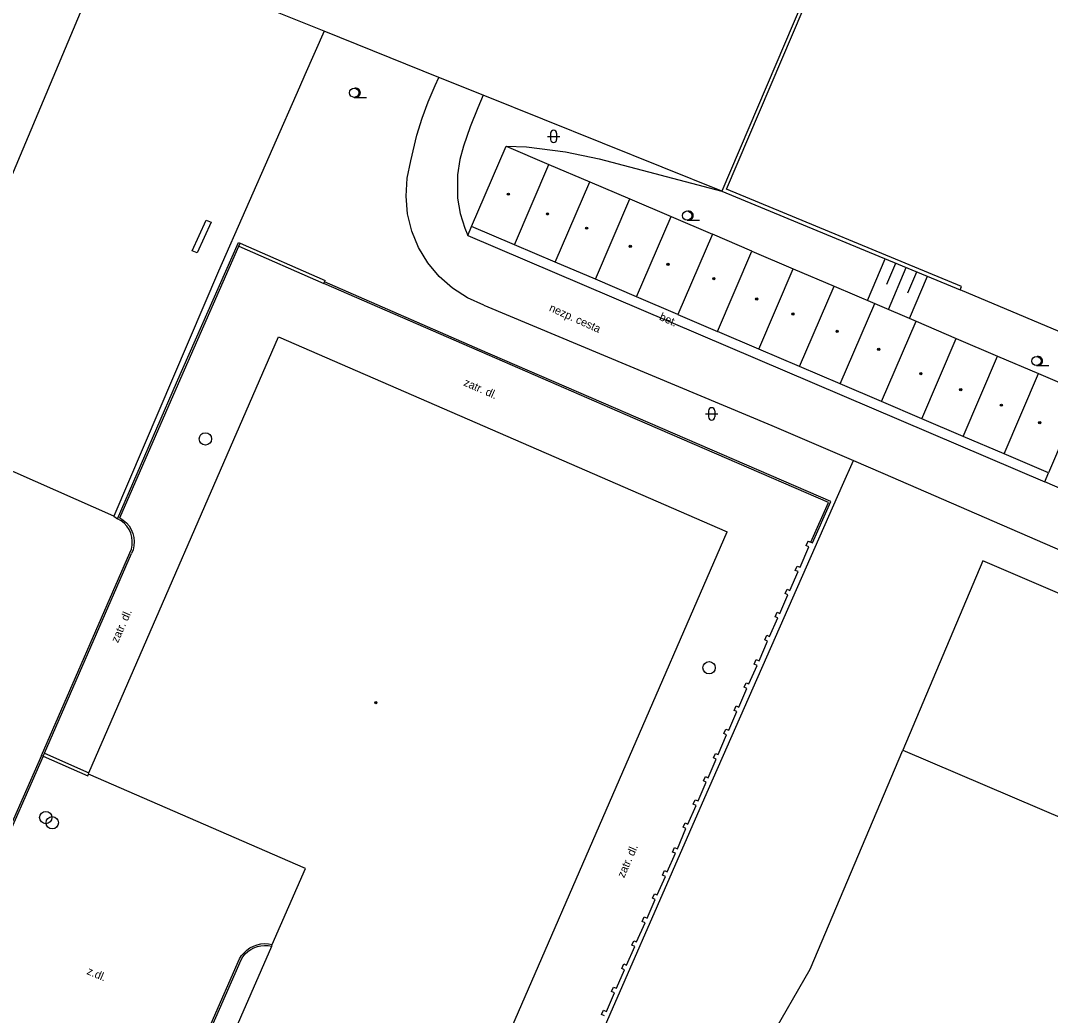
# Model space of a CAD drawing. Extents: x -596024 to -594475, y -1163820 to -1161957.
# Drawn here: x -594855 to -594771.3, y -1162292 to -1162211.2 of the extents above; entities that cross this region are included whole.
import ezdxf

# ---------------------------------------------------------------- set-up
doc = ezdxf.new("R2010")
doc.units = 0
for name, color, linetype in [('Level 10', 7, 'Continuous'), ('Level 11', 7, 'Continuous'), ('Level 14', 7, 'Continuous'), ('Level 15', 7, 'Continuous'), ('Level 27', 7, 'Continuous'), ('Level 36', 7, 'Continuous'), ('Level 39', 7, 'Continuous'), ('Level 40', 7, 'Continuous'), ('Level 5', 7, 'Continuous'), ('Level 7', 7, 'Continuous')]:
    doc.layers.add(name, color=color, linetype=linetype)

msp = doc.modelspace()

# ---------------------------------------------------------------- linework, layer by layer
at = {"layer": 'Level 10'}
for points in [[(-594790.84, -1162288.2), (-594783.33, -1162270.4)], [(-594783.33, -1162270.4), (-594763.33, -1162278.94)], [(-594853.14, -1162270.89), (-594860.69, -1162288.01)], [(-594853.14, -1162270.89), (-594849.52, -1162272.49)], [(-594849.52, -1162272.49), (-594849.46, -1162272.36)], [(-594837.2, -1162287.37), (-594837.03, -1162287.1), (-594836.83, -1162286.86), (-594836.6, -1162286.64), (-594836.35, -1162286.46), (-594836.06, -1162286.32), (-594835.77, -1162286.21), (-594835.46, -1162286.14), (-594835.15, -1162286.12), (-594834.83, -1162286.14), (-594834.53, -1162286.2)], [(-594841.81, -1162297.87), (-594837.2, -1162287.37)], [(-594797.39, -1162299.58), (-594790.84, -1162288.2)]]:
    msp.add_lwpolyline(points, dxfattribs=at)
at = {"layer": 'Level 11'}
for points in [[(-594817.36, -1162234.27), (-594818.68, -1162233.68), (-594819.89, -1162232.89), (-594820.97, -1162231.93), (-594821.9, -1162230.82), (-594822.65, -1162229.58), (-594823.2, -1162228.24), (-594823.54, -1162226.84), (-594823.67, -1162225.4), (-594823.58, -1162223.95), (-594823.28, -1162222.54), (-594822.78, -1162220.45), (-594822.36, -1162219.08), (-594821.87, -1162217.74), (-594821.31, -1162216.42), (-594821, -1162215.77)], [(-594817.4, -1162217.22), (-594817.85, -1162218.23), (-594818.46, -1162219.78), (-594818.99, -1162221.36), (-594819.29, -1162222.43), (-594819.5, -1162223.68), (-594819.49, -1162225.57), (-594819.28, -1162226.81), (-594818.9, -1162228.02), (-594818.65, -1162228.6)], [(-594839.9, -1162227.35), (-594839.51, -1162227.53), (-594840.64, -1162230.02), (-594841.04, -1162229.84), (-594839.9, -1162227.35)], [(-594818.65, -1162228.6), (-594818.34, -1162227.87)], [(-594818.65, -1162228.6), (-594771.8, -1162248.61)], [(-594847.11, -1162251.62), (-594842.3, -1162240.58), (-594837.29, -1162229.17)], [(-594846.92, -1162251.55), (-594842.16, -1162240.64), (-594837.25, -1162229.46)], [(-594837.29, -1162229.17), (-594837.15, -1162229.23)], [(-594837.25, -1162229.46), (-594837.15, -1162229.23)], [(-594837.25, -1162229.46), (-594830.35, -1162232.5)], [(-594837.15, -1162229.23), (-594830.25, -1162232.27)], [(-594830.35, -1162232.5), (-594830.29, -1162232.37)], [(-594790.78, -1162253.52), (-594789.37, -1162250.29), (-594805.87, -1162243.14), (-594817.71, -1162238.01), (-594830.35, -1162232.5)], [(-594830.29, -1162232.37), (-594830.25, -1162232.27)], [(-594790.65, -1162253.57), (-594789.18, -1162250.22), (-594805.81, -1162243), (-594817.65, -1162237.88), (-594830.29, -1162232.37)], [(-594817.36, -1162234.27), (-594793.95, -1162244.04)], [(-594793.95, -1162244.04), (-594787.33, -1162246.87)], [(-594771.8, -1162248.61), (-594771.49, -1162247.88)], [(-594768.91, -1162249.85), (-594771.8, -1162248.61)], [(-594847.39, -1162251.41), (-594847.11, -1162251.62)], [(-594846.09, -1162254.37), (-594845.97, -1162254.07), (-594845.91, -1162253.75), (-594845.9, -1162253.42), (-594845.93, -1162253.1), (-594846.02, -1162252.78), (-594846.16, -1162252.48), (-594846.34, -1162252.21), (-594846.56, -1162251.98), (-594846.82, -1162251.78), (-594847.11, -1162251.62)], [(-594846.92, -1162251.55), (-594846.64, -1162251.73), (-594846.38, -1162251.95), (-594846.16, -1162252.2), (-594845.99, -1162252.49), (-594845.86, -1162252.8), (-594845.77, -1162253.13), (-594845.74, -1162253.46), (-594845.77, -1162253.8), (-594845.84, -1162254.13), (-594845.96, -1162254.44)], [(-594791.02, -1162253.42), (-594791.19, -1162253.78)], [(-594791.02, -1162253.42), (-594790.78, -1162253.52)], [(-594790.78, -1162253.52), (-594790.65, -1162253.57)], [(-594853.28, -1162270.83), (-594846.09, -1162254.37)], [(-594853.04, -1162270.66), (-594845.96, -1162254.44)], [(-594791.67, -1162255.55), (-594790.96, -1162253.89)], [(-594790.96, -1162253.89), (-594791.19, -1162253.78)], [(-594776.82, -1162255.03), (-594783.33, -1162270.4)], [(-594752.13, -1162265.61), (-594776.82, -1162255.03)], [(-594792.49, -1162257.43), (-594791.83, -1162255.91)], [(-594792.06, -1162255.81), (-594791.9, -1162255.45)], [(-594791.83, -1162255.91), (-594792.06, -1162255.81)], [(-594791.9, -1162255.45), (-594791.67, -1162255.55)], [(-594793.31, -1162259.31), (-594792.65, -1162257.79)], [(-594792.88, -1162257.69), (-594792.72, -1162257.33)], [(-594792.65, -1162257.79), (-594792.88, -1162257.69)], [(-594792.72, -1162257.33), (-594792.49, -1162257.43)], [(-594793.7, -1162259.57), (-594793.54, -1162259.21)], [(-594793.47, -1162259.67), (-594793.7, -1162259.57)], [(-594793.54, -1162259.21), (-594793.31, -1162259.31)], [(-594794.14, -1162261.18), (-594793.47, -1162259.67)], [(-594794.53, -1162261.45), (-594794.37, -1162261.08)], [(-594794.37, -1162261.08), (-594794.14, -1162261.18)], [(-594795, -1162263.15), (-594794.3, -1162261.56)], [(-594794.3, -1162261.56), (-594794.53, -1162261.45)], [(-594795.82, -1162265.03), (-594795.16, -1162263.52)], [(-594795.39, -1162263.42), (-594795.23, -1162263.05)], [(-594795.16, -1162263.52), (-594795.39, -1162263.42)], [(-594795.23, -1162263.05), (-594795, -1162263.15)], [(-594796.64, -1162266.91), (-594795.98, -1162265.4)], [(-594796.21, -1162265.3), (-594796.05, -1162264.93)], [(-594795.98, -1162265.4), (-594796.21, -1162265.3)], [(-594796.05, -1162264.93), (-594795.82, -1162265.03)], [(-594797.03, -1162267.18), (-594796.87, -1162266.81)], [(-594796.87, -1162266.81), (-594796.64, -1162266.91)], [(-594797.46, -1162268.79), (-594796.8, -1162267.28)], [(-594796.8, -1162267.28), (-594797.03, -1162267.18)], [(-594797.85, -1162269.06), (-594797.69, -1162268.69)], [(-594797.69, -1162268.69), (-594797.46, -1162268.79)], [(-594798.31, -1162270.77), (-594797.63, -1162269.17)], [(-594797.63, -1162269.17), (-594797.85, -1162269.06)], [(-594853.28, -1162270.83), (-594860.83, -1162287.95)], [(-594853.14, -1162270.89), (-594853.04, -1162270.66)], [(-594853.04, -1162270.66), (-594849.42, -1162272.26)], [(-594799.13, -1162272.65), (-594798.47, -1162271.14)], [(-594798.7, -1162271.03), (-594798.54, -1162270.67)], [(-594798.47, -1162271.14), (-594798.7, -1162271.03)], [(-594798.54, -1162270.67), (-594798.31, -1162270.77)], [(-594799.52, -1162272.91), (-594799.36, -1162272.55)], [(-594799.29, -1162273.01), (-594799.52, -1162272.91)], [(-594799.36, -1162272.55), (-594799.13, -1162272.65)], [(-594799.95, -1162274.53), (-594799.29, -1162273.01)], [(-594800.34, -1162274.79), (-594800.18, -1162274.43)], [(-594800.18, -1162274.43), (-594799.95, -1162274.53)], [(-594800.77, -1162276.41), (-594800.11, -1162274.89)], [(-594800.11, -1162274.89), (-594800.34, -1162274.79)], [(-594801.16, -1162276.67), (-594801, -1162276.31)], [(-594801, -1162276.31), (-594800.77, -1162276.41)], [(-594801.63, -1162278.41), (-594800.94, -1162276.78)], [(-594800.94, -1162276.78), (-594801.16, -1162276.67)], [(-594802.45, -1162280.29), (-594801.79, -1162278.78)], [(-594802.02, -1162278.68), (-594801.86, -1162278.31)], [(-594801.79, -1162278.78), (-594802.02, -1162278.68)], [(-594801.86, -1162278.31), (-594801.63, -1162278.41)], [(-594802.84, -1162280.56), (-594802.68, -1162280.19)], [(-594802.68, -1162280.19), (-594802.45, -1162280.29)], [(-594803.27, -1162282.17), (-594802.61, -1162280.66)], [(-594802.61, -1162280.66), (-594802.84, -1162280.56)], [(-594803.66, -1162282.44), (-594803.5, -1162282.07)], [(-594803.5, -1162282.07), (-594803.27, -1162282.17)], [(-594804.09, -1162284.05), (-594803.43, -1162282.54)], [(-594803.43, -1162282.54), (-594803.66, -1162282.44)], [(-594804.94, -1162285.99), (-594804.26, -1162284.43)], [(-594804.48, -1162284.32), (-594804.32, -1162283.95)], [(-594804.26, -1162284.43), (-594804.48, -1162284.32)], [(-594804.32, -1162283.95), (-594804.09, -1162284.05)], [(-594837.07, -1162287.44), (-594836.92, -1162287.19), (-594836.73, -1162286.96), (-594836.51, -1162286.76), (-594836.28, -1162286.59), (-594836.02, -1162286.46), (-594835.74, -1162286.36), (-594835.45, -1162286.29), (-594835.16, -1162286.27), (-594834.87, -1162286.28), (-594834.58, -1162286.33)], [(-594805.76, -1162287.87), (-594805.1, -1162286.36)], [(-594805.33, -1162286.26), (-594805.17, -1162285.89)], [(-594805.1, -1162286.36), (-594805.33, -1162286.26)], [(-594805.17, -1162285.89), (-594804.94, -1162285.99)], [(-594841.67, -1162297.92), (-594837.07, -1162287.44)], [(-594806.15, -1162288.14), (-594805.99, -1162287.77)], [(-594805.99, -1162287.77), (-594805.76, -1162287.87)], [(-594806.58, -1162289.75), (-594805.92, -1162288.24)], [(-594805.92, -1162288.24), (-594806.15, -1162288.14)], [(-594806.97, -1162290.01), (-594806.81, -1162289.65)], [(-594806.81, -1162289.65), (-594806.58, -1162289.75)], [(-594807.4, -1162291.63), (-594806.74, -1162290.12)], [(-594806.74, -1162290.12), (-594806.97, -1162290.01)], [(-594807.79, -1162291.89), (-594807.63, -1162291.53)], [(-594807.56, -1162291.98), (-594807.79, -1162291.89)], [(-594807.63, -1162291.53), (-594807.4, -1162291.63)]]:
    msp.add_lwpolyline(points, dxfattribs=at)
at = {"layer": 'Level 14'}
for points in [[(-594815.55, -1162221.34), (-594813.89, -1162221.41)], [(-594813.89, -1162221.41), (-594810.72, -1162221.81)], [(-594810.72, -1162221.81), (-594807.99, -1162222.38)], [(-594807.99, -1162222.38), (-594798.03, -1162225.01)]]:
    msp.add_lwpolyline(points, dxfattribs=at)
at = {"layer": 'Level 15'}
for points in [[(-594786.19, -1162233.89), (-594784.75, -1162230.5)], [(-594784.62, -1162232.55), (-594783.89, -1162230.86)], [(-594784.49, -1162234.61), (-594783.04, -1162231.21)], [(-594782.91, -1162233.27), (-594782.18, -1162231.56)], [(-594782.79, -1162235.34), (-594781.33, -1162231.92)]]:
    msp.add_lwpolyline(points, dxfattribs=at)
at = {"layer": 'Level 27'}
for centre in [(-594839.97, -1162245.13), (-594799.06, -1162263.71), (-594852.93, -1162275.88), (-594852.4, -1162276.3)]:
    msp.add_circle(centre, 0.5, dxfattribs=at)
at = {"layer": 'Level 36'}
for p, q in [((-594827.88, -1162217.385), (-594826.88, -1162217.385)), ((-594811.936, -1162220.306), (-594811.936, -1162220.806)), ((-594811.436, -1162220.306), (-594811.436, -1162220.806)), ((-594812.186, -1162220.556), (-594811.186, -1162220.556)), ((-594800.84, -1162227.365), (-594799.84, -1162227.365)), ((-594772.47, -1162239.175), (-594771.47, -1162239.175)), ((-594799.096, -1162242.846), (-594799.096, -1162243.346)), ((-594798.596, -1162242.846), (-594798.596, -1162243.346)), ((-594799.346, -1162243.096), (-594798.346, -1162243.096))]:
    msp.add_line(p, q, dxfattribs=at)
for centre in [(-594827.88, -1162217.01), (-594800.84, -1162226.99), (-594772.47, -1162238.8)]:
    msp.add_circle(centre, 0.375, dxfattribs=at)
for centre, radius, start, end in [((-594827.755, -1162217.01), 0.375, 260.40593, 99.59407), ((-594811.686, -1162220.306), 0.25, 0, 180), ((-594811.686, -1162220.806), 0.25, 180, 0), ((-594800.715, -1162226.99), 0.375, 260.40593, 99.59407), ((-594772.345, -1162238.8), 0.375, 260.40593, 99.59407), ((-594798.846, -1162242.846), 0.25, 0, 180), ((-594798.846, -1162243.346), 0.25, 180, 0)]:
    msp.add_arc(centre, radius, start, end, dxfattribs=at)
at = {"layer": 'Level 39'}
for centre, radius in [((-594815.36, -1162225.25), 0.09), ((-594815.36, -1162225.25), 0.0398), ((-594812.18, -1162226.85), 0.09), ((-594812.18, -1162226.85), 0.0398), ((-594809, -1162228.01), 0.09), ((-594809, -1162228.01), 0.0398), ((-594805.46, -1162229.48), 0.09), ((-594805.46, -1162229.48), 0.0398), ((-594802.4, -1162230.95), 0.09), ((-594802.4, -1162230.95), 0.0398), ((-594798.67, -1162232.11), 0.09), ((-594798.67, -1162232.11), 0.0398), ((-594795.19, -1162233.76), 0.09), ((-594795.19, -1162233.76), 0.0398), ((-594792.25, -1162234.98), 0.09), ((-594792.25, -1162234.98), 0.0398), ((-594788.65, -1162236.39), 0.09), ((-594788.65, -1162236.39), 0.0398), ((-594785.28, -1162237.86), 0.09), ((-594785.28, -1162237.86), 0.0398), ((-594781.86, -1162239.82), 0.09), ((-594781.86, -1162239.82), 0.0398), ((-594778.62, -1162241.13), 0.09), ((-594778.62, -1162241.13), 0.0398), ((-594775.32, -1162242.39), 0.09), ((-594775.32, -1162242.39), 0.0398), ((-594772.2, -1162243.8), 0.09), ((-594772.2, -1162243.8), 0.0398), ((-594826.12, -1162266.55), 0.09), ((-594826.12, -1162266.55), 0.0398)]:
    msp.add_circle(centre, radius, dxfattribs=at)
at = {"layer": 'Level 5'}
for points in [[(-594848.71, -1162207.07), (-594855.8, -1162223.97)], [(-594818.34, -1162227.87), (-594815.55, -1162221.34)], [(-594815.55, -1162221.34), (-594812.07, -1162222.84)], [(-594814.87, -1162229.35), (-594812.07, -1162222.84)], [(-594812.07, -1162222.84), (-594808.75, -1162224.24)], [(-594811.56, -1162230.76), (-594808.75, -1162224.24)], [(-594808.75, -1162224.24), (-594805.49, -1162225.64)], [(-594808.28, -1162232.16), (-594805.49, -1162225.64)], [(-594805.49, -1162225.64), (-594802.14, -1162227.07)], [(-594804.94, -1162233.59), (-594802.14, -1162227.07)], [(-594802.14, -1162227.07), (-594798.79, -1162228.51)], [(-594814.87, -1162229.35), (-594818.34, -1162227.87)], [(-594798.79, -1162228.51), (-594801.59, -1162235.02)], [(-594795.58, -1162229.88), (-594798.79, -1162228.51)], [(-594811.56, -1162230.76), (-594814.87, -1162229.35)], [(-594798.37, -1162236.4), (-594795.58, -1162229.88)], [(-594795.58, -1162229.88), (-594792.22, -1162231.31)], [(-594808.28, -1162232.16), (-594811.56, -1162230.76)], [(-594795.02, -1162237.83), (-594792.22, -1162231.31)], [(-594792.22, -1162231.31), (-594788.91, -1162232.73)], [(-594804.94, -1162233.59), (-594808.28, -1162232.16)], [(-594791.71, -1162239.25), (-594788.91, -1162232.73)], [(-594788.91, -1162232.73), (-594785.6, -1162234.14)], [(-594801.59, -1162235.02), (-594804.94, -1162233.59)], [(-594788.4, -1162240.66), (-594785.6, -1162234.14)], [(-594785.6, -1162234.14), (-594782.25, -1162235.57)], [(-594801.59, -1162235.02), (-594798.37, -1162236.4)], [(-594785.05, -1162242.09), (-594782.25, -1162235.57)], [(-594782.25, -1162235.57), (-594779, -1162236.97)], [(-594849.42, -1162272.26), (-594834.02, -1162236.84)], [(-594834.02, -1162236.84), (-594797.59, -1162252.67)], [(-594795.02, -1162237.83), (-594798.37, -1162236.4)], [(-594781.78, -1162243.49), (-594779, -1162236.97)], [(-594779, -1162236.97), (-594775.64, -1162238.4)], [(-594791.71, -1162239.25), (-594795.02, -1162237.83)], [(-594778.43, -1162244.92), (-594775.64, -1162238.4)], [(-594775.64, -1162238.4), (-594772.31, -1162239.82)], [(-594788.4, -1162240.66), (-594791.71, -1162239.25)], [(-594775.1, -1162246.34), (-594772.31, -1162239.82)], [(-594772.31, -1162239.82), (-594768.7, -1162241.36)], [(-594785.05, -1162242.09), (-594788.4, -1162240.66)], [(-594768.7, -1162241.36), (-594771.49, -1162247.88)], [(-594781.78, -1162243.49), (-594785.05, -1162242.09)], [(-594778.43, -1162244.92), (-594781.78, -1162243.49)], [(-594775.1, -1162246.34), (-594778.43, -1162244.92)], [(-594771.49, -1162247.88), (-594775.1, -1162246.34)], [(-594815.62, -1162294.16), (-594797.59, -1162252.67)], [(-594849.46, -1162272.36), (-594849.42, -1162272.26)], [(-594831.84, -1162280.02), (-594849.46, -1162272.36)], [(-594834.53, -1162286.2), (-594831.84, -1162280.02)], [(-594839.6, -1162297.87), (-594834.58, -1162286.33)], [(-594834.58, -1162286.33), (-594834.53, -1162286.2)]]:
    msp.add_lwpolyline(points, dxfattribs=at)
at = {"layer": 'Level 7'}
for points in [[(-594790.75, -1162207.89), (-594798.03, -1162225.01)], [(-594797.64, -1162224.85), (-594790.47, -1162208.01)], [(-594830.33, -1162212.02), (-594834.65, -1162210.28)], [(-594830.33, -1162212.02), (-594831.89, -1162215.56), (-594832.33, -1162216.56)], [(-594821, -1162215.77), (-594830.33, -1162212.02)], [(-594817.4, -1162217.22), (-594821, -1162215.77)], [(-594832.33, -1162216.56), (-594838.89, -1162231.51), (-594847.39, -1162251.41), (-594869.57, -1162241.6), (-594892.87, -1162231.48), (-594908.27, -1162224.57)], [(-594798.03, -1162225.01), (-594817.4, -1162217.22)], [(-594798.03, -1162225.01), (-594778.66, -1162233.02)], [(-594778.55, -1162232.74), (-594797.64, -1162224.85)], [(-594778.66, -1162233.02), (-594778.55, -1162232.74)], [(-594757.85, -1162241.8), (-594778.66, -1162233.02)], [(-594790.44, -1162253.91), (-594788.22, -1162248.88), (-594787.33, -1162246.87)], [(-594787.33, -1162246.87), (-594784.94, -1162247.92)], [(-594784.94, -1162247.92), (-594739.92, -1162267.46)], [(-594799.41, -1162274.25), (-594790.44, -1162253.91)], [(-594809.73, -1162297.85), (-594799.41, -1162274.25)]]:
    msp.add_lwpolyline(points, dxfattribs=at)

# ---------------------------------------------------------------- texts
at = {"layer": 'Level 40'}
for s, rotation, p in [('nezp. cesta', 335.94, (-594812.1, -1162234.71)), ('bet.', 336.23, (-594803.15, -1162235.44)), ('zatr. dl.', 336.47, (-594819.05, -1162240.77)), ('zatr. dl.', 66.27, (-594847.07, -1162261.74)), ('zatr. dl.', 66.27, (-594805.96, -1162280.83)), ('z.dl.', 336.94, (-594849.65, -1162288.58))]:
    msp.add_text(s, height=0.65, rotation=rotation, dxfattribs=at).set_placement(p)

doc.saveas('drawing.dxf')
